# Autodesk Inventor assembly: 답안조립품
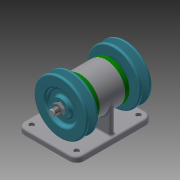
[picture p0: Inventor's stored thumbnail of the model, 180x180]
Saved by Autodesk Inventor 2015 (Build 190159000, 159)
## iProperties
Created: 2019-09
Part Number: 답안조립품
Document SubType Name: Assembly
Designer: now
Author: now
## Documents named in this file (10)
- C:\Users\now\Desktop\490904V1034\답안조립품.iam
- C:\Users\now\Desktop\490904V1034\V-벨트풀리.ipt
- C:\Users\now\Desktop\490904V1034\너트 M10x1.ipt
- C:\Users\now\Desktop\490904V1034\베어링 6004.ipt
- C:\Users\now\Desktop\490904V1034\본체.ipt
- C:\Users\now\Desktop\490904V1034\볼트 M4.ipt
- C:\Users\now\Desktop\490904V1034\오일 실 17 30 5.ipt
- C:\Users\now\Desktop\490904V1034\축.ipt
- C:\Users\now\Desktop\490904V1034\커버.ipt
- C:\Users\now\Desktop\490904V1034\키 5 x 5 x 12.ipt
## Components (2 placed, 1 different names)
1. V-벨트풀리:1 — 각도:2
2. V-벨트풀리:2 — 각도:4
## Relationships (2: Angle 2)
- 각도:2 [Angle]: V-벨트풀리:1
- 각도:4 [Angle]: V-벨트풀리:2
